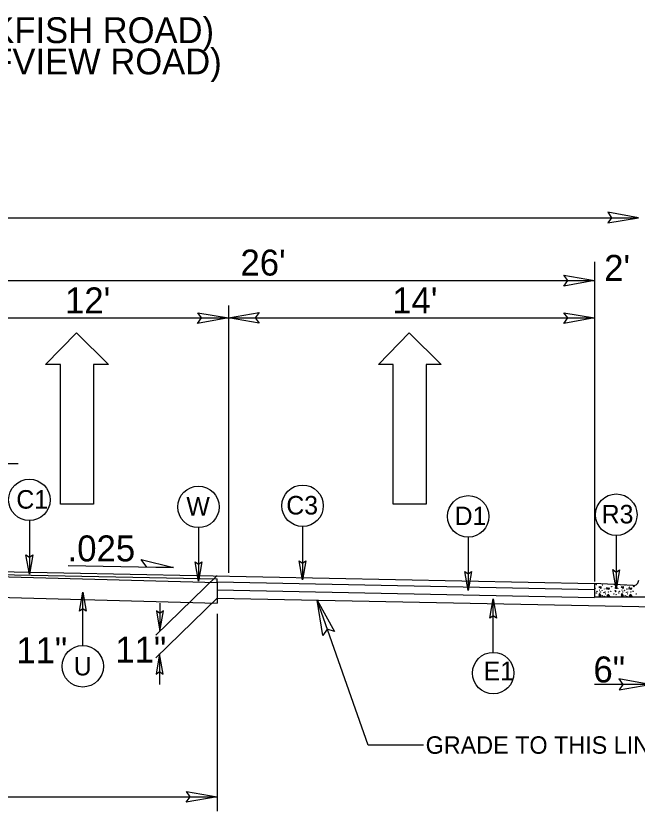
# Model space of a CAD drawing. Extents: x 958711 to 962106, y 831169 to 840840.
# Drawn here: x 961520 to 961706.7, y 838596.5 to 838835.4 of the extents above; entities that cross this region are included whole.
import ezdxf

# ---------------------------------------------------------------- set-up
doc = ezdxf.new("R2010")
doc.units = 0
for name, color, linetype in [('Old_Level_1', 7, 'Continuous'), ('Old_Level_11', 7, 'Continuous'), ('Old_Level_3', 7, 'Continuous'), ('Prop Dimension Text', 7, 'Continuous'), ('Prop Lane Arrow CELL', 7, 'Continuous'), ('Typical ID Circle CELL', 7, 'Continuous'), ('Typical Terminator CELL', 7, 'Continuous'), ('Typical Text ID Circle CELL', 7, 'Continuous')]:
    doc.layers.add(name, color=color, linetype=linetype)

# ---------------------------------------------------------------- blocks, each defined once
blk = doc.blocks.new('Lane Arrow Through')
at = {"layer": 'Prop Lane Arrow CELL'}
for p, q in [((-3.15, 1.6), (-3.15, 3.1)), ((-3.15, 3.1), (0, 0)), ((-17.15, 1.6), (-3.15, 1.6)), ((-17.15, -1.7), (-17.15, 1.6)), ((0, 0), (-3.15, -3.2)), ((-3.15, -1.7), (-17.15, -1.7)), ((-3.15, -3.2), (-3.15, -1.7))]:
    blk.add_line(p, q, dxfattribs=at)

msp = doc.modelspace()

# ---------------------------------------------------------------- linework, layer by layer
at = {"layer": 'Old_Level_1'}
for p, q in [((961140.72, 838774.8), (961707.16, 838774.8)), ((961693.95, 838761.49), (961693.95, 838665.52)), ((961693.95, 838761.49), (961693.95, 838666.02)), ((961490.42, 838755.91), (961693.95, 838755.91)), ((961583.9, 838748.41), (961583.9, 838668.12)), ((961490.42, 838744.66), (961583.9, 838744.66)), ((961583.9, 838744.66), (961693.95, 838744.66)), ((961497.02, 838700.96), (961520.75, 838700.96)), ((961490.42, 838668.96), (961693.95, 838664.84)), ((961535.77, 838670.27), (961567.38, 838669.64)), ((961497.02, 838667.96), (961580.53, 838666.27)), ((961580.56, 838667.31), (961562.09, 838649.38)), ((961580.53, 838665.15), (961580.53, 838666.27)), ((961580.53, 838665.41), (961693.95, 838663.12)), ((961580.53, 838665.15), (961580.53, 838658.97)), ((961580.53, 838662.98), (961693.95, 838660.69)), ((961580.53, 838660.49), (961562.06, 838642.56)), ((961563.3, 838658.92), (961563.3, 838650.56)), ((961580.53, 838660.49), (961716.89, 838657.73)), ((961625.88, 838616.3), (961610.57, 838659.88)), ((961580.53, 838655.73), (961580.53, 838596.48)), ((961563.23, 838643.74), (961563.23, 838634.51)), ((961710.52, 838634.55), (961693.92, 838634.55)), ((961642.49, 838616.3), (961625.88, 838616.3)), ((961259.53, 838600.76), (961580.53, 838600.76))]:
    msp.add_line(p, q, dxfattribs=at)
for points in [[(961422.25, 838669.47), (961580.53, 838665.15)], [(961422.41, 838663.28), (961580.53, 838658.97)]]:
    msp.add_lwpolyline(points, dxfattribs=at)
at = {"layer": 'Old_Level_11'}
for p, q in [((961559.37, 838669.8), (961557.64, 838672.06)), ((961557.64, 838672.06), (961567.38, 838669.64)), ((961567.38, 838669.64), (961559.37, 838669.8))]:
    msp.add_line(p, q, dxfattribs=at)
msp.add_lwpolyline([(961612.27, 838649.29), (961610.57, 838659.88), (961615.78, 838650.42), (961613.58, 838651.11)], close=True, dxfattribs=at)
at = {"layer": 'Old_Level_3'}
for p, q in [((961705.49, 838664.27), (961693.95, 838664.84)), ((961693.95, 838664.84), (961693.95, 838660.86)), ((961695.21, 838663.92), (961695.79, 838663.94)), ((961695.79, 838663.36), (961695.21, 838663.92)), ((961695.79, 838663.94), (961695.79, 838663.36)), ((961697.47, 838663.31), (961698.31, 838663.54)), ((961698.31, 838663.54), (961698.21, 838663.05)), ((961701.93, 838663.92), (961702.52, 838663.94)), ((961702.52, 838663.36), (961701.93, 838663.92)), ((961702.52, 838663.94), (961702.52, 838663.36)), ((961704.2, 838663.31), (961705.03, 838663.54)), ((961705.03, 838663.54), (961704.94, 838663.05)), ((961705.49, 838664.27), (961705.49, 838664.27)), ((961695.42, 838661.89), (961695.24, 838661.28)), ((961695.24, 838661.28), (961695.88, 838661.24)), ((961695.88, 838661.24), (961695.42, 838661.89)), ((961698.21, 838663.05), (961697.47, 838663.31)), ((961698.15, 838661.58), (961697.59, 838661.19)), ((961697.59, 838661.19), (961698.49, 838660.97)), ((961698.49, 838660.97), (961698.15, 838661.58)), ((961702.15, 838661.89), (961701.97, 838661.28)), ((961701.97, 838661.28), (961702.61, 838661.24)), ((961702.61, 838661.24), (961702.15, 838661.89)), ((961704.94, 838663.05), (961704.2, 838663.31)), ((961704.88, 838661.58), (961704.32, 838661.19)), ((961704.32, 838661.19), (961705.22, 838660.97)), ((961705.22, 838660.97), (961704.88, 838661.58)), ((961693.95, 838660.86), (961710.52, 838660.86))]:
    msp.add_line(p, q, dxfattribs=at)
for centre in [(961694.16, 838663.46), (961694.43, 838664.56), (961696.37, 838664.38), (961697.63, 838663.76), (961699.07, 838663.92), (961700.15, 838663.52), (961700.89, 838663.46), (961704.35, 838663.76), (961705.8, 838663.92), (961694.5, 838661.99), (961694.65, 838662.53), (961695.45, 838662.87), (961695.7, 838662.32), (961696.22, 838662.78), (961696.37, 838661.25), (961696.8, 838662.11), (961696.89, 838661), (961696.92, 838663.18), (961697.1, 838662.29), (961697.19, 838661.77), (961698.15, 838662.29), (961698.8, 838662.56), (961699.75, 838661.68), (961700.18, 838662.72), (961700.27, 838662.45), (961700.42, 838661.52), (961701.22, 838661.99), (961701.38, 838662.53), (961702.18, 838662.87), (961702.42, 838662.32), (961702.95, 838662.78), (961703.1, 838661.25), (961703.53, 838662.11), (961703.62, 838661), (961703.65, 838663.18), (961703.83, 838662.29), (961703.92, 838661.77), (961704.88, 838662.29), (961705.52, 838662.56), (961706.48, 838661.68)]:
    msp.add_circle(centre, 0.0432, dxfattribs=at)
for centre, radius, start, end in [((961705.57, 838665.9), 1.64, 267.1376, 358.9266), ((961700.06, 838664.53), 0.0432, 164.1199, 10.1626), ((961703.1, 838664.38), 0.0432, 162.062, 12.2205)]:
    msp.add_arc(centre, radius, start, end, dxfattribs=at)
at = {"layer": 'Typical ID Circle CELL'}
for p, q in [((961524.09, 838683.78), (961524.09, 838667.69)), ((961574.9, 838681.67), (961574.9, 838665.58)), ((961606.2, 838682.02), (961606.2, 838665.93)), ((961655.97, 838678.82), (961655.97, 838662.73)), ((961700.47, 838679.33), (961700.47, 838663.24)), ((961540.14, 838646.23), (961540.14, 838662.32)), ((961663.48, 838644.17), (961663.48, 838660.26))]:
    msp.add_line(p, q, dxfattribs=at)
for centre in [(961524.09, 838690), (961606.2, 838688.24), (961574.9, 838687.89), (961655.97, 838685.04), (961700.47, 838685.55), (961540.14, 838640), (961663.48, 838637.95)]:
    msp.add_circle(centre, 6.23, dxfattribs=at)
at = {"layer": 'Typical Terminator CELL'}
for points in [[(961697.94, 838773.21), (961707.16, 838774.8), (961697.88, 838776.44), (961699.06, 838774.8)], [(961684.73, 838757.5), (961693.95, 838755.91), (961684.68, 838754.27), (961685.86, 838755.91)], [(961574.67, 838746.25), (961583.9, 838744.66), (961574.62, 838743.02), (961575.8, 838744.66)], [(961593.12, 838743.08), (961583.9, 838744.66), (961593.17, 838746.3), (961591.99, 838744.66)], [(961684.73, 838746.25), (961693.95, 838744.66), (961684.68, 838743.02), (961685.86, 838744.66)], [(961525.09, 838673.46), (961524.09, 838667.69), (961523.07, 838673.49), (961524.09, 838672.75)], [(961575.89, 838671.35), (961574.9, 838665.58), (961573.88, 838671.38), (961574.9, 838670.64)], [(961607.19, 838671.69), (961606.2, 838665.93), (961605.17, 838671.72), (961606.2, 838670.99)], [(961656.97, 838668.49), (961655.97, 838662.73), (961654.95, 838668.53), (961655.97, 838667.79)], [(961701.46, 838669.01), (961700.47, 838663.24), (961699.45, 838669.04), (961700.47, 838668.3)], [(961539.15, 838656.55), (961540.14, 838662.32), (961541.17, 838656.52), (961540.14, 838657.26)], [(961662.49, 838654.5), (961663.48, 838660.26), (961664.5, 838654.46), (961663.48, 838655.2)], [(961562.25, 838656.63), (961563.3, 838650.56), (961564.38, 838656.66), (961563.3, 838655.89)], [(961564.28, 838637.67), (961563.23, 838643.74), (961562.15, 838637.64), (961563.23, 838638.41)], [(961701.3, 838632.96), (961710.52, 838634.55), (961701.25, 838636.19), (961702.43, 838634.55)], [(961571.31, 838602.35), (961580.53, 838600.76), (961571.26, 838599.12), (961572.44, 838600.76)]]:
    msp.add_lwpolyline(points, close=True, dxfattribs=at)

# ---------------------------------------------------------------- block references
at = {"layer": 'Old_Level_1', "xscale": 3, "yscale": 3, "rotation": 90}
for p in [(961538.26, 838740.16), (961638.26, 838740.16)]:
    msp.add_blockref('Lane Arrow Through', p, dxfattribs=at)

# ---------------------------------------------------------------- texts
at = {"layer": 'Old_Level_1'}
msp.add_text('GRADE TO THIS LINE', height=5.2473, dxfattribs=at).set_placement((961643.17, 838613.71))
at = {"layer": 'Old_Level_11'}
msp.add_text('11"', height=7.801, dxfattribs=at).set_placement((961549.92, 838641.11))
at = {"layer": 'Old_Level_3'}
msp.add_text("2'", height=7.801, dxfattribs=at).set_placement((961696.82, 838755.82))
at = {"layer": 'Prop Dimension Text'}
for s, height, rotation, p in [('-L- SR 1112 (ROCKFISH ROAD)', 7.7675, 0, (961427.22, 838827.26)), ('-Y- SR 1115 (GOLFVIEW ROAD)', 7.7675, 0, (961427.22, 838817.87)), ("26'", 7.801, 0, (961587.52, 838757.41)), ("12'", 7.801, 0, (961534.81, 838746.04)), ("14'", 7.801, 0, (961633.13, 838746.04)), ('.025', 7.801, 360, (961535.58, 838671.52)), ('11"', 7.801, 0, (961520.15, 838640.92)), ('6"', 7.801, 0, (961693.6, 838635.15))]:
    msp.add_text(s, height=height, rotation=rotation, dxfattribs=at).set_placement(p)
at = {"layer": 'Typical Text ID Circle CELL'}
for s, height, p in [('C1', 5.572, (961520.18, 838687.37)), ('W', 5.57, (961571.28, 838685.26)), ('C3', 5.572, (961601.31, 838685.61)), ('D1', 5.572, (961651.89, 838682.41)), ('R3', 5.572, (961696.09, 838682.92)), ('U', 5.57, (961537.44, 838637.26)), ('E1', 5.572, (961660.59, 838635.81))]:
    msp.add_text(s, height=height, dxfattribs=at).set_placement(p)

doc.saveas('drawing.dxf')
